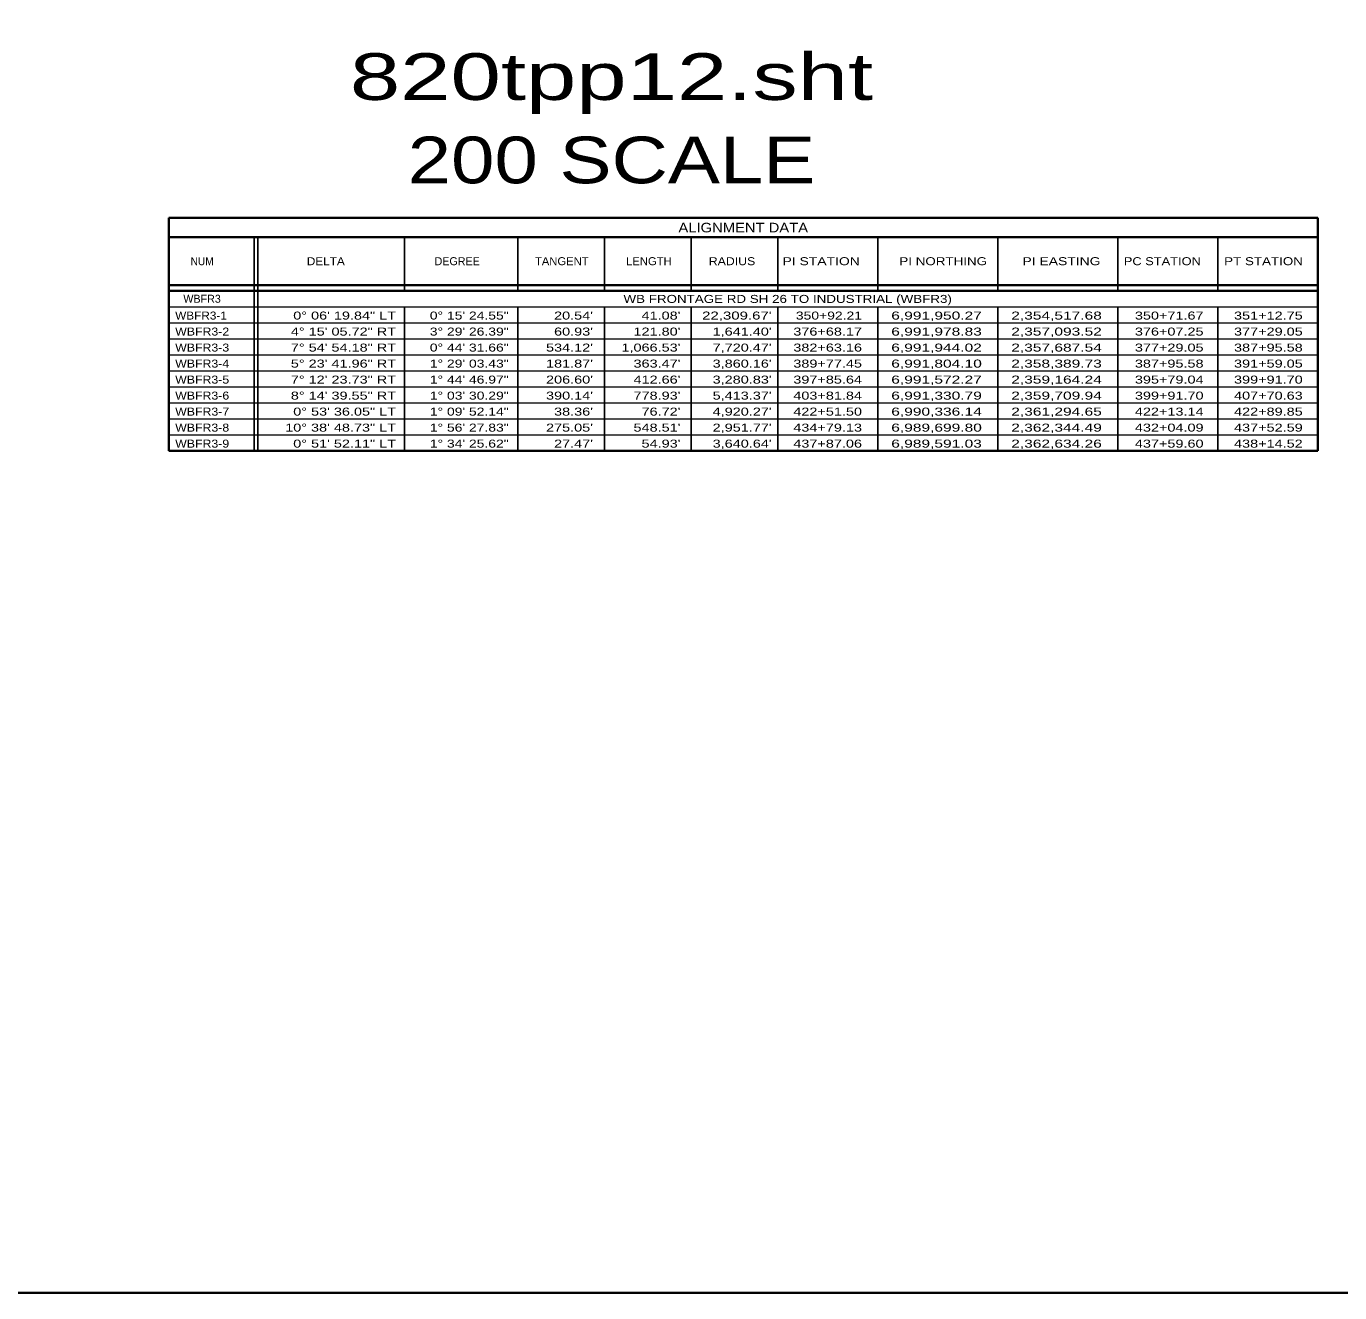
# Model space of a CAD drawing. Extents: x 1953053 to 1967065, y 7363860 to 7371201.
# Drawn here: x 1963762 to 1965732, y 7363860 to 7365759 of the extents above; entities that cross this region are included whole.
import ezdxf
from ezdxf.enums import TextEntityAlignment as Align

# ---------------------------------------------------------------- set-up
doc = ezdxf.new("R2010")
doc.units = 0
doc.header["$LTSCALE"] = 4.8
doc.layers.add('10', color=7, linetype='Continuous')
doc.layers.add('12', color=7, linetype='Continuous', lineweight=25)
doc.layers.add('62', color=7, linetype='Continuous', lineweight=35)

msp = doc.modelspace()

# ---------------------------------------------------------------- linework, layer by layer
at = {"layer": '12', "lineweight": 35}
for p, q in [((1965699.375, 7365471.266), (1963976.043, 7365471.266)), ((1963976.043, 7365471.265), (1963976.043, 7365122.133)), ((1965699.375, 7365122.133), (1965699.375, 7365471.265)), ((1963976.043, 7365442.466), (1965699.375, 7365442.466)), ((1963976.043, 7365370.466), (1965699.375, 7365370.466)), ((1963976.043, 7365362.133), (1965699.375, 7365362.133)), ((1963976.043, 7365122.133), (1965699.375, 7365122.133))]:
    msp.add_line(p, q, dxfattribs=at)
at = {"layer": '12'}
for p, q in [((1964103.888, 7365442.465), (1964103.888, 7365122.133)), ((1964109.375, 7365442.465), (1964109.375, 7365122.133)), ((1964329.375, 7365442.465), (1964329.375, 7365362.133)), ((1964499.375, 7365442.465), (1964499.375, 7365362.133)), ((1964629.375, 7365442.465), (1964629.375, 7365362.133)), ((1964759.375, 7365442.465), (1964759.375, 7365362.133)), ((1964889.375, 7365442.465), (1964889.375, 7365362.133)), ((1965039.375, 7365442.465), (1965039.375, 7365362.133)), ((1965219.375, 7365442.465), (1965219.375, 7365362.133)), ((1965399.375, 7365442.465), (1965399.375, 7365362.133)), ((1965549.375, 7365442.465), (1965549.375, 7365362.133)), ((1964103.888, 7365420.866), (1964103.888, 7365144.913)), ((1964329.375, 7365338.133), (1964329.375, 7365122.133)), ((1964499.375, 7365338.133), (1964499.375, 7365122.133)), ((1964629.375, 7365338.133), (1964629.375, 7365122.133)), ((1964759.375, 7365338.133), (1964759.375, 7365122.133)), ((1964889.375, 7365338.133), (1964889.375, 7365122.133)), ((1965039.375, 7365338.133), (1965039.375, 7365122.133)), ((1965219.375, 7365338.133), (1965219.375, 7365122.133)), ((1965399.375, 7365338.133), (1965399.375, 7365122.133)), ((1965549.375, 7365338.133), (1965549.375, 7365122.133))]:
    msp.add_line(p, q, dxfattribs=at)
at = {"layer": '12', "lineweight": 13}
for p, q in [((1963976.043, 7365338.133), (1965699.375, 7365338.133)), ((1963976.043, 7365314.133), (1965699.375, 7365314.133)), ((1963976.043, 7365290.133), (1965699.375, 7365290.133)), ((1963976.043, 7365266.133), (1965699.375, 7365266.133)), ((1963976.043, 7365242.133), (1965699.375, 7365242.133)), ((1963976.043, 7365218.133), (1965699.375, 7365218.133)), ((1963976.043, 7365194.133), (1965699.375, 7365194.133)), ((1963976.043, 7365170.133), (1965699.375, 7365170.133)), ((1963976.043, 7365146.133), (1965699.375, 7365146.133))]:
    msp.add_line(p, q, dxfattribs=at)
at = {"layer": '62'}
msp.add_lwpolyline([(1953052.784, 7371201.108), (1967065.314, 7371201.108), (1967065.314, 7363859.877), (1953052.784, 7363859.877)], close=True, dxfattribs=at)

# ---------------------------------------------------------------- texts
at = {"layer": '10'}
msp.add_text('WBFR3', height=12, dxfattribs=at).set_placement((1963997.885, 7365344.176))
at = {"layer": '10', "width": 1.25}
msp.add_text('WB FRONTAGE RD SH 26 TO INDUSTRIAL (WBFR3)', height=12, dxfattribs=at).set_placement((1964904.375, 7365343.927), align=Align.CENTER)
at = {"layer": '10'}
for s, width, p in [('WBFR3-1', 1.1, (1963985.664, 7365318.96)), ('WBFR3-2', 1.15, (1963985.664, 7365294.96)), ('WBFR3-3', 1.15, (1963985.664, 7365270.96)), ('WBFR3-4', 1.15, (1963985.664, 7365246.96)), ('WBFR3-5', 1.15, (1963985.664, 7365222.96)), ('WBFR3-6', 1.15, (1963985.664, 7365198.96)), ('WBFR3-7', 1.15, (1963985.664, 7365174.96)), ('WBFR3-8', 1.15, (1963985.664, 7365150.96)), ('WBFR3-9', 1.15, (1963985.664, 7365126.96))]:
    msp.add_text(s, height=12, dxfattribs=dict(at, width=width)).set_placement(p)
for s, width, p in [('0° 06\' 19.84" LT', 1.35, (1964316.897, 7365318.96)), ('0° 15\' 24.55"', 1.3, (1964485.892, 7365318.96)), ("20.54'", 1.35, (1964612.302, 7365318.96)), ("41.08'", 1.35, (1964743.499, 7365318.96)), ("22,309.67'", 1.4, (1964880.268, 7365318.96)), ('350+92.21', 1.3, (1965015.812, 7365318.96)), ('6,991,950.27', 1.45, (1965195.577, 7365318.96)), ('2,354,517.68', 1.45, (1965375.577, 7365318.96)), ('350+71.67', 1.35, (1965528.155, 7365318.96)), ('351+12.75', 1.35, (1965676.887, 7365318.96)), ('4° 15\' 05.72" RT', 1.35, (1964316.897, 7365294.96)), ('3° 29\' 26.39"', 1.3, (1964485.892, 7365294.96)), ("60.93'", 1.35, (1964612.302, 7365294.96)), ("121.80'", 1.35, (1964743.499, 7365294.96)), ("1,641.40'", 1.35, (1964880.268, 7365294.96)), ('376+68.17', 1.35, (1965015.812, 7365294.96)), ('6,991,978.83', 1.45, (1965195.577, 7365294.96)), ('2,357,093.52', 1.45, (1965375.577, 7365294.96)), ('376+07.25', 1.35, (1965528.155, 7365294.96)), ('377+29.05', 1.35, (1965676.887, 7365294.96)), ('7° 54\' 54.18" RT', 1.35, (1964316.897, 7365270.96)), ('0° 44\' 31.66"', 1.3, (1964485.892, 7365270.96)), ("534.12'", 1.35, (1964612.302, 7365270.96)), ("1,066.53'", 1.35, (1964743.499, 7365270.96)), ("7,720.47'", 1.35, (1964880.268, 7365270.96)), ('382+63.16', 1.35, (1965015.812, 7365270.96)), ('6,991,944.02', 1.45, (1965195.577, 7365270.96)), ('2,357,687.54', 1.45, (1965375.577, 7365270.96)), ('377+29.05', 1.35, (1965528.155, 7365270.96)), ('387+95.58', 1.35, (1965676.887, 7365270.96)), ('5° 23\' 41.96" RT', 1.35, (1964316.897, 7365246.96)), ('1° 29\' 03.43"', 1.3, (1964485.892, 7365246.96)), ("181.87'", 1.35, (1964612.302, 7365246.96)), ("363.47'", 1.35, (1964743.499, 7365246.96)), ("3,860.16'", 1.35, (1964880.268, 7365246.96)), ('389+77.45', 1.35, (1965015.812, 7365246.96)), ('6,991,804.10', 1.45, (1965195.577, 7365246.96)), ('2,358,389.73', 1.45, (1965375.577, 7365246.96)), ('387+95.58', 1.35, (1965528.155, 7365246.96)), ('391+59.05', 1.35, (1965676.887, 7365246.96)), ('7° 12\' 23.73" RT', 1.35, (1964316.897, 7365222.96)), ('1° 44\' 46.97"', 1.3, (1964485.892, 7365222.96)), ("206.60'", 1.35, (1964612.302, 7365222.96)), ("412.66'", 1.35, (1964743.499, 7365222.96)), ("3,280.83'", 1.35, (1964880.268, 7365222.96)), ('397+85.64', 1.35, (1965015.812, 7365222.96)), ('6,991,572.27', 1.45, (1965195.577, 7365222.96)), ('2,359,164.24', 1.45, (1965375.577, 7365222.96)), ('395+79.04', 1.35, (1965528.155, 7365222.96)), ('399+91.70', 1.35, (1965676.887, 7365222.96)), ('8° 14\' 39.55" RT', 1.35, (1964316.897, 7365198.96)), ('1° 03\' 30.29"', 1.3, (1964485.892, 7365198.96)), ("390.14'", 1.35, (1964612.302, 7365198.96)), ("778.93'", 1.35, (1964743.499, 7365198.96)), ("5,413.37'", 1.35, (1964880.268, 7365198.96)), ('403+81.84', 1.35, (1965015.812, 7365198.96)), ('6,991,330.79', 1.45, (1965195.577, 7365198.96)), ('2,359,709.94', 1.45, (1965375.577, 7365198.96)), ('399+91.70', 1.35, (1965528.155, 7365198.96)), ('407+70.63', 1.35, (1965676.887, 7365198.96)), ('0° 53\' 36.05" LT', 1.35, (1964316.897, 7365174.96)), ('1° 09\' 52.14"', 1.3, (1964485.892, 7365174.96)), ("38.36'", 1.35, (1964612.302, 7365174.96)), ("76.72'", 1.35, (1964743.499, 7365174.96)), ("4,920.27'", 1.35, (1964880.268, 7365174.96)), ('422+51.50', 1.35, (1965015.812, 7365174.96)), ('6,990,336.14', 1.45, (1965195.577, 7365174.96)), ('2,361,294.65', 1.45, (1965375.577, 7365174.96)), ('422+13.14', 1.35, (1965528.155, 7365174.96)), ('422+89.85', 1.35, (1965676.887, 7365174.96)), ('10° 38\' 48.73" LT', 1.35, (1964316.897, 7365150.96)), ('1° 56\' 27.83"', 1.3, (1964485.892, 7365150.96)), ("275.05'", 1.35, (1964612.302, 7365150.96)), ("548.51'", 1.35, (1964743.499, 7365150.96)), ("2,951.77'", 1.35, (1964880.268, 7365150.96)), ('434+79.13', 1.35, (1965015.812, 7365150.96)), ('6,989,699.80', 1.45, (1965195.577, 7365150.96)), ('2,362,344.49', 1.45, (1965375.577, 7365150.96)), ('432+04.09', 1.35, (1965528.155, 7365150.96)), ('437+52.59', 1.35, (1965676.887, 7365150.96)), ('0° 51\' 52.11" LT', 1.35, (1964316.897, 7365126.96)), ('1° 34\' 25.62"', 1.3, (1964485.892, 7365126.96)), ("27.47'", 1.35, (1964612.302, 7365126.96)), ("54.93'", 1.35, (1964743.499, 7365126.96)), ("3,640.64'", 1.35, (1964880.268, 7365126.96)), ('437+87.06', 1.35, (1965015.812, 7365126.96)), ('6,989,591.03', 1.45, (1965195.577, 7365126.96)), ('2,362,634.26', 1.45, (1965375.577, 7365126.96)), ('437+59.60', 1.35, (1965528.155, 7365126.96)), ('438+14.52', 1.35, (1965676.887, 7365126.96))]:
    msp.add_text(s, height=12, dxfattribs=dict(at, width=width)).set_placement(p, align=Align.RIGHT)
at = {"layer": '12'}
for s, height, width, p in [('ALIGNMENT DATA', 14.4, 1.15, (1964837.709, 7365449.665)), ('NUM', 12, 0.95, (1964026.044, 7365400.462)), ('DELTA', 12, 1.1, (1964211.572, 7365400.465)), ('TANGENT', 12, 1.05, (1964565.519, 7365400.465)), ('LENGTH', 12, 1.05, (1964696.2, 7365400.465)), ('RADIUS', 12, 1.15, (1964820.858, 7365400.465)), ('PI STATION', 12, 1.3, (1964954.57, 7365400.465)), ('PI NORTHING', 12, 1.25, (1965137.647, 7365400.465)), ('PI EASTING', 12, 1.3, (1965315.038, 7365400.465)), ('PC STATION', 12, 1.2, (1965466.341, 7365400.465)), ('PT STATION', 12, 1.25, (1965618.112, 7365400.465))]:
    msp.add_text(s, height=height, dxfattribs=dict(at, width=width)).set_placement(p, align=Align.CENTER)
msp.add_text('DEGREE', height=12, dxfattribs=at).set_placement((1964408.612, 7365400.465), align=Align.CENTER)
at = {"layer": '62'}
for s, width, p in [('820tpp12.sht', 1.45, (1964640.099, 7365648.265)), ('200 SCALE', 1.25, (1964640.099, 7365523.265))]:
    msp.add_text(s, height=70, dxfattribs=dict(at, width=width)).set_placement(p, align=Align.CENTER)

doc.saveas('drawing.dxf')
